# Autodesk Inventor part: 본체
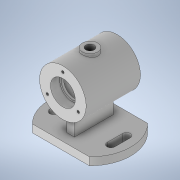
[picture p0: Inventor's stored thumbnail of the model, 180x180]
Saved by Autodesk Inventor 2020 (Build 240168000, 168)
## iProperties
Created: 2021-09
Part Number: 본체
Material: 일반
Document SubType Name: Modeling
Designer: Administrator
Density: 1 g/cm^3
Appearance: 기본값
Author: Administrator
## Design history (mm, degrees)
sketch "스케치1"
  geometry: L1 (-37.5, -36.742)-(-37.5, 36.742); L2 (37.5, 36.742)-(37.5, -36.742); A1 r 52.5 centre (0, 0) between (-37.5, -36.742) and (-37.5, 36.742); 1 further point
  constraints: 4 end point, 4 point on circle, 2 vertical, 1 centre point, 1 coincident
  dimensions: "d0" = 105 diameter of A1; "d1" = 75 distance between parallel lines of L2 L1; "d2" = 37.5 distance from line of point (0, 0) L2 (= 0.5 x d1)
extrude "돌출1" new body sketch "스케치1" distance "d3" = 10; taper "d4" = 0 deg
sketch "스케치2"
  geometry: L1 (36.742, 0)-(-36.742, 0) reference; C1 r 30 at (0, 62); 2 further points
  constraints: 1 centre point, 1 midpoint, 1 vertical alignment
  dimensions: "d5" = 62 distance from line of L1 C1.centre; "d6" = 60 diameter of C1
extrude "돌출2" join sketch "스케치2" stored distance "d7" = 70; taper "d8" = 0 deg
node "작업 평면1"
sketch "스케치3"
  geometry: C1 r 10 at (0, 0); 1 further point
  constraints: 1 centre point, 1 coincident
  dimensions: "d10" = 20 diameter of C1
extrude "돌출3" join sketch "스케치3" stored distance "d11" = 70; taper "d12" = 0 deg
sketch "스케치4"
  geometry: L1 (-25, 3.472)-(25, 3.472); L2 (25, 3.472)-(25, 64.583); L3 (25, 64.583)-(-25, 64.583); L4 (-25, 64.583)-(-25, 3.472); L5 (-25, 3.472)-(25, 64.583); L6 (25, 3.472)-(-25, 64.583); 3 further points
  constraints: 12 end point, 3 midpoint, 2 parallel, 1 horizontal, 1 perpendicular, 1 vertical alignment
  dimensions: "d13" = 50 distance of L1.start L1.end
extrude "돌출4" join sketch "스케치4" stored distance "d14" = 10; taper "d15" = 0 deg
sketch "스케치5"
  geometry: L1 (-10, 37)-(10, 37); L2 (-10, 32)-(10, 32); L3 (10, 42)-(-10, 42); A1 r 5 centre (-10, 37) between (-10, 42) and (-10, 32); A2 r 5 centre (10, 37) between (10, 32) and (10, 42); 2 further points
  constraints: 8 end point, 4 point on circle, 4 tangent, 2 centre point, 1 horizontal, 1 midpoint, 1 parallel, 1 vertical alignment
  dimensions: "d16" = 5 radius of A2; "d17" = 37 distance from line of point (0, 0) L1; "d18" = 20 distance of L1.start L1.end
extrude "돌출5" cut sketch "스케치5" extent not by distance; stored distance "d19" = 0; taper "d20" = 0 deg
sketch "스케치6"
  geometry: C1 r 10 at (0, 0) reference; 2 further points
  constraints: 1 coincident
hole "구멍1" sketch "스케치6" at (0, 0) diameter "d21" = 10.917; stored, may be unused: countersink angle "d25" = 90 deg, drill point angle "d27" = 118 deg; dims "d22" = 24, "d23" = 4, "d24" = 2, "d26" = 29.1
sketch "스케치7"
  geometry: L1 (35, 32)-(35, 92) reference; L2 (35, 62)-(-89.458, 62); L3 (35, 78)-(23, 78); L4 (23, 78)-(23, 76); L5 (23, 76)-(20, 76); L6 (20, 76)-(20, 87); L7 (20, 87)-(-20, 87); L8 (-20, 87)-(-20, 76); L9 (-20, 76)-(-23, 76); L10 (-23, 76)-(-23, 78); L11 (-23, 78)-(-35, 78); L12 (-35, 92)-(-35, 32) reference; 2 further points
  constraints: 20 end point, 6 perpendicular, 5 point on line, 2 horizontal, 1 midpoint
  dimensions: "d28" = 50 diameter of L7 L2; "d29" = 28 diameter of L5 L2; "d30" = 32 diameter of L3 L2; "d31" = 12 distance of L3.start L3.end; "d32" = 12 distance of L10.end L11.end (= d31); "d33" = 40 distance of L6.end L7.end; "d34" = 3 distance of L4.end L5.end; "d35" = 3 distance of L8.end L9.end
revolve "회전1" sketch "스케치7" stored, may be unused: angle "d36" = 90 deg
sketch "스케치8"
  geometry: C1 r 16 at (0, 0) reference; 2 further points
  constraints: 1 horizontal alignment
  dimensions: "d37" = 23 distance of point (-23, 0) C1.centre
hole "구멍2" sketch "스케치8" at (-23, 0) diameter "d38" = 3.242; stored, may be unused: countersink angle "d42" = 90 deg, drill point angle "d44" = 118 deg; dims "d39" = 8, "d40" = 4, "d41" = 2, "d43" = 10
node "솔리드1"
mirror "미러1"
pattern_circular "원형 패턴1" dims angle "d46" = 360 deg
mirror "미러2"
feature "A9D066F2-1C7D-4E18-AEED-F7BC21143FA4" dims "d21" = 10.917, "d22" = 24, "d23" = 4, "d24" = 2, "d25" = 90 deg, "d26" = 29.1, "d27" = 118 deg
other parameters: "d9" = 95
